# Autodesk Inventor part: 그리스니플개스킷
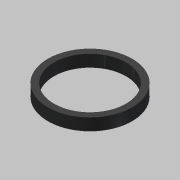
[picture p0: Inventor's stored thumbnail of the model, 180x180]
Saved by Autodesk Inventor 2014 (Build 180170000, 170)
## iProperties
Created: 2019-05
Part Number: 그리스니플개스킷
Material: 고무
Document SubType Name: Modeling
Designer: mduedu
Density: 1 g/cm^3
Appearance: Rubber - Black - Version 1.1
Author: mduedu
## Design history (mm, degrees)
sketch "스케치1"
  geometry: C1 r 3 at (0, 0); C2 r 3.5 at (0, 0); 1 further point
  constraints: 2 centre point, 2 coincident
  dimensions: "d0" = 6 diameter of C1; "d1" = 7 diameter of C2
extrude "돌출1" new body sketch "스케치1" distance "d2" = 1; taper "d3" = 0 deg
node "솔리드1"
